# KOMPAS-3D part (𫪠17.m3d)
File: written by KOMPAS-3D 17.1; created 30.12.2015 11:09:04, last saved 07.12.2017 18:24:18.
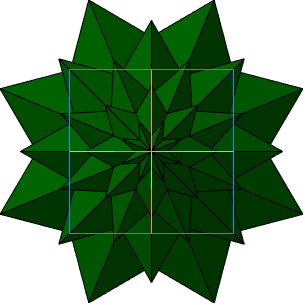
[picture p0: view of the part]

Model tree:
1. Эскиз:1
2. Операция выдавливания:1
     Расстояние 1 = 20
3. Массив по сетке:1  (with: Операция выдавливания:1, Эскиз:1)  (labels: v40_2_1_D; v40_2_1_a; v40_2_1_d)  (5 pattern instances)
     Шаг 1 = 20; Угол раствора = 90

Expressions: 90/4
